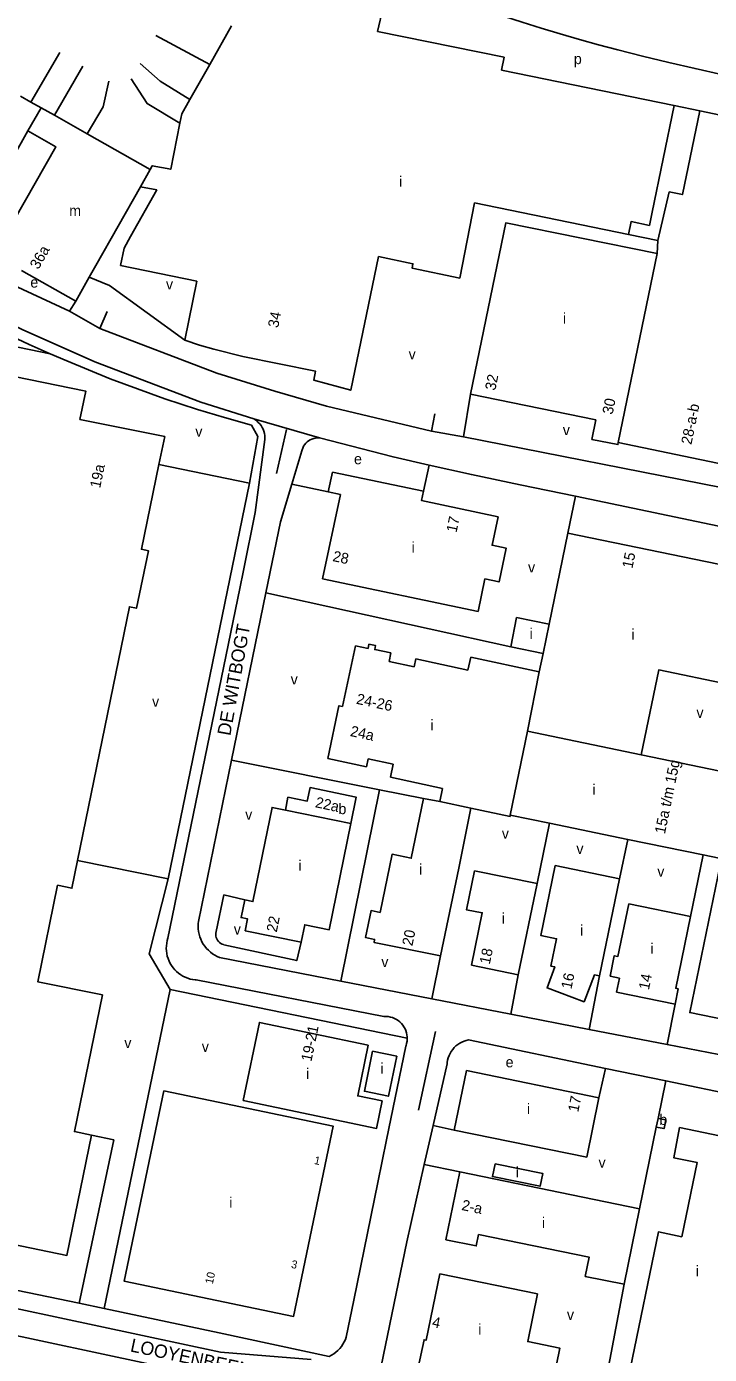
# Model space of a CAD drawing. Extents: x 157699 to 159683, y 381451 to 383293.
# Drawn here: x 158121.9 to 158378.5, y 382412.9 to 382912.1 of the extents above; entities that cross this region are included whole.
import ezdxf

# ---------------------------------------------------------------- set-up
doc = ezdxf.new("R2010")
doc.units = 0
for name, color, linetype in [('BLT_Basislijn', 7, 'Continuous'), ('BLT_Bebouwing', 7, 'Continuous'), ('BLT_Centroide', 7, 'Continuous'), ('BLT_Huisnummer', 7, 'Continuous'), ('BLT_Huisnummer_reeks', 7, 'Continuous'), ('BLT_Huisnummer_zonder_bebouwing', 7, 'Continuous'), ('BLT_Onderverdeling_panden', 7, 'Continuous'), ('BLT_Plantopo', 7, 'Continuous'), ('BLT_Straatnaam', 7, 'Continuous'), ('BLT_Vlakafsluiter', 7, 'Continuous')]:
    doc.layers.add(name, color=color, linetype=linetype)

msp = doc.modelspace()

# ---------------------------------------------------------------- linework, layer by layer
at = {"layer": 'BLT_Basislijn'}
for p, q in [((158170.52, 382908.69), (158190.73, 382897.79)), ((158134.47, 382902.3), (158123.51, 382883.71)), ((158143.12, 382897.15), (158132.36, 382878.72)), ((158365.26, 382882.45), (158374.91, 382880.36)), ((158374.91, 382880.36), (158410.62, 382872.97)), ((158348.09, 382833.93), (158359.11, 382831.68)), ((158359.11, 382831.68), (158358.91, 382826.72)), ((158153.11, 382814.79), (158145.48, 382817.84)), ((158181.37, 382794.18), (158153.11, 382814.79)), ((158066.51, 382802.08), (158130.82, 382789.08)), ((158288.77, 382773.83), (158286.11, 382757.88)), ((158219.56, 382760.56), (158215.88, 382744.12)), ((158286.11, 382757.88), (158382.94, 382738.83)), ((158211.43, 382756.88), (158207.86, 382729.4)), ((158225.36, 382752.63), (158221.58, 382740.04)), ((158271.09, 382737.39), (158273.16, 382747.23)), ((158175.13, 382591.65), (158205.69, 382740.41)), ((158221.58, 382740.04), (158217.35, 382725.93)), ((158235.29, 382737.16), (158221.58, 382740.04)), ((158328.18, 382735.5), (158307.46, 382739.82)), ((158325.37, 382721.64), (158328.18, 382735.5)), ((158410.45, 382718.37), (158328.18, 382735.5)), ((158203.38, 382707.6), (158207.86, 382729.4)), ((158217.35, 382725.93), (158211.88, 382699.26)), ((158203.38, 382707.6), (158202, 382700.87)), ((158202, 382700.87), (158175.02, 382569.41)), ((158211.88, 382699.26), (158198.96, 382636.32)), ((158303.85, 382678.9), (158211.88, 382699.26)), ((158198.96, 382636.32), (158186.5, 382575.59)), ((158198.96, 382636.32), (158254.52, 382625.1)), ((158271.1, 382621.91), (158254.52, 382625.1)), ((158313.75, 382589.93), (158318.49, 382612.56)), ((158249.98, 382602.82), (158239.99, 382553.27)), ((158344.72, 382591.73), (158347.83, 382606.52)), ((158376.2, 382600.68), (158371.43, 382577.47)), ((158168.01, 382563.5), (158175.13, 382591.65)), ((158175.92, 382550.09), (158168.01, 382563.5)), ((158194.44, 382562.13), (158239.99, 382553.27)), ((158277.52, 382562.68), (158274.2, 382546.62)), ((158185.61, 382553.66), (158256.21, 382539.93)), ((158239.99, 382553.27), (158274.2, 382546.62)), ((158306.71, 382555.65), (158303.91, 382540.84)), ((158337.21, 382555.17), (158333.36, 382535.11)), ((158174.41, 382542.8), (158175.92, 382550.09)), ((158264.97, 382531.75), (158175.92, 382550.09)), ((158151.05, 382430.2), (158174.41, 382542.8)), ((158274.2, 382546.62), (158303.91, 382540.84)), ((158365.62, 382544.54), (158362.62, 382529.42)), ((158303.91, 382540.84), (158333.36, 382535.11)), ((158275.65, 382534.29), (158269.2, 382504.67)), ((158333.36, 382535.11), (158362.62, 382529.42)), ((158264.4, 382528.72), (158257.23, 382493.62)), ((158288.04, 382531.15), (158339.51, 382520.44)), ((158362.62, 382529.42), (158419.43, 382518.37)), ((158336.93, 382509.32), (158339.51, 382520.44)), ((158339.51, 382520.44), (158362.15, 382515.73)), ((158359.22, 382501.62), (158362.15, 382515.73)), ((158362.15, 382515.73), (158440.61, 382499.4)), ((158282.61, 382497.22), (158274.7, 382499.01)), ((158352.25, 382467.67), (158358.54, 382498.35)), ((158257.23, 382493.62), (158253.94, 382477.52)), ((158284.75, 382481.5), (158271.37, 382484.25)), ((158079.72, 382444.87), (158141.73, 382432.11)), ((158337.32, 382391.27), (158346.43, 382439.27)), ((158167.06, 382409.46), (158078.71, 382428.33)), ((158141.73, 382432.11), (158151.05, 382430.2)), ((158151.05, 382430.2), (158194.34, 382420.96)), ((158194.34, 382420.96), (158235.68, 382412.15)), ((158228.89, 382411.03), (158194.81, 382413.76))]:
    msp.add_line(p, q, dxfattribs=at)
for points in [[(158344.05, 382903.29), (158336.84, 382905.22), (158329.65, 382907.23), (158322.49, 382909.31), (158315.35, 382911.47), (158308.22, 382913.7), (158301.13, 382916.01), (158294.06, 382918.4), (158287.01, 382920.87), (158279.99, 382923.4), (158273, 382926.02), (158266.04, 382928.71), (158259.11, 382931.47), (158252.21, 382934.31), (158245.33, 382937.22), (158238.49, 382940.2), (158231.68, 382943.26), (158224.91, 382946.39), (158219.94, 382948.75)], [(158432.83, 382884.22), (158422.84, 382886.04), (158412.88, 382887.94), (158402.92, 382889.92), (158392.99, 382891.97), (158383.07, 382894.1), (158373.17, 382896.31), (158363.28, 382898.6), (158353.41, 382900.97), (158344.05, 382903.29)], [(158164.55, 382898.18), (158172.17, 382891.59), (158183.28, 382884.62)], [(158161.25, 382892.41), (158167.23, 382883.14), (158179.55, 382875.74)], [(158152.81, 382891.59), (158150.75, 382881.9), (158144.73, 382871.74)], [(158130.82, 382789.08), (158122.95, 382792.52), (158103.06, 382801.86), (158093.21, 382806.75), (158070.33, 382818.61)], [(158207.29, 382764.61), (158187.44, 382770.88), (158147.52, 382786.08), (158120.25, 382798.17), (158071.88, 382821.87)], [(158138.07, 382805.1), (158117.02, 382814.81)], [(158140.4, 382808.83), (158138.07, 382805.1)], [(158152.23, 382804.94), (158149.43, 382798.58)], [(158149.43, 382798.58), (158193.46, 382781.8), (158215.23, 382775.05), (158234.68, 382769.4), (158274.12, 382759.98)], [(158205.69, 382740.41), (158208.77, 382757.97), (158206.39, 382762.19), (158196.25, 382765.08), (158186.13, 382768.18), (158173.93, 382772.19), (158153.39, 382779.68), (158137.04, 382786.36), (158130.82, 382789.08)], [(158207.29, 382764.61), (158208.4, 382763.81), (158209.01, 382763.29), (158209.56, 382762.71), (158210.04, 382762.07), (158210.46, 382761.39), (158210.81, 382760.67), (158211.09, 382759.92), (158211.29, 382759.15), (158211.42, 382758.36), (158211.46, 382757.56), (158211.43, 382756.88)], [(158274.12, 382759.98), (158275.37, 382766.54)], [(158231.99, 382757.52), (158230.51, 382757.38), (158229.82, 382757.24), (158229.15, 382757.01), (158228.51, 382756.72), (158227.9, 382756.35), (158227.35, 382755.92), (158226.84, 382755.43), (158226.39, 382754.88), (158226.01, 382754.29), (158225.7, 382753.65), (158225.45, 382752.99), (158225.36, 382752.63)], [(158273.16, 382747.23), (158259.62, 382750.28), (158231.99, 382757.52)], [(158171.64, 382747.4), (158205.69, 382740.41)], [(158307.46, 382739.82), (158289.11, 382743.64), (158273.16, 382747.23)], [(158254.52, 382625.1), (158249.98, 382602.82)], [(158141.08, 382598.6), (158175.13, 382591.65)], [(158203.89, 382583.79), (158196.07, 382585.67), (158193.19, 382571.86)], [(158194.44, 382562.13), (158193.52, 382562.54), (158192.63, 382563.01), (158191.79, 382563.55), (158190.99, 382564.16), (158190.24, 382564.83), (158189.54, 382565.56), (158188.91, 382566.34), (158188.34, 382567.17), (158187.84, 382568.04), (158187.41, 382568.95), (158187.05, 382569.89), (158186.77, 382570.86), (158186.56, 382571.84), (158186.43, 382572.84), (158186.39, 382573.85), (158186.42, 382574.85), (158186.5, 382575.59)], [(158175.02, 382569.41), (158174.76, 382568.47), (158174.57, 382567.51), (158174.46, 382566.53), (158174.42, 382565.55), (158174.47, 382564.57), (158174.6, 382563.6), (158174.81, 382562.64), (158175.09, 382561.7), (158175.45, 382560.79), (158175.89, 382559.91), (158176.39, 382559.07), (158176.96, 382558.27), (158177.6, 382557.52), (158178.29, 382556.83), (158179.03, 382556.19), (158179.83, 382555.62), (158180.67, 382555.11), (158181.55, 382554.68), (158182.46, 382554.31), (158183.4, 382554.03), (158184.36, 382553.82), (158185.33, 382553.68), (158185.61, 382553.66)], [(158193.19, 382571.86), (158193.08, 382571.31), (158193.05, 382570.74), (158193.09, 382570.18), (158193.22, 382569.63), (158193.43, 382569.1), (158193.7, 382568.61), (158194.05, 382568.15), (158194.45, 382567.76), (158194.9, 382567.42), (158195.4, 382567.15), (158195.93, 382566.95), (158196.07, 382566.92)], [(158196.07, 382566.92), (158223.47, 382560.94), (158225.12, 382567.88)], [(158256.21, 382539.93), (158257.02, 382539.95), (158257.83, 382539.88), (158258.62, 382539.74), (158259.4, 382539.52), (158260.15, 382539.22), (158260.88, 382538.85), (158261.56, 382538.42), (158262.19, 382537.91), (158262.77, 382537.35), (158263.29, 382536.73), (158263.75, 382536.06), (158264.15, 382535.35), (158264.46, 382534.61), (158264.71, 382533.84), (158264.88, 382533.05), (158264.96, 382532.24), (158264.97, 382531.75)], [(158264.97, 382531.75), (158264.97, 382531.43), (158264.9, 382530.62), (158264.75, 382529.83), (158264.52, 382529.05), (158264.4, 382528.72)], [(158288.04, 382531.15), (158287.17, 382530.95), (158286.33, 382530.67), (158285.51, 382530.32), (158284.72, 382529.9), (158283.98, 382529.4), (158283.28, 382528.85), (158282.64, 382528.23), (158282.05, 382527.55), (158281.53, 382526.83), (158281.07, 382526.06), (158280.68, 382525.26), (158280.37, 382524.42), (158280.13, 382523.56), (158279.97, 382522.68), (158279.92, 382522.19)], [(158279.92, 382522.19), (158274.7, 382499.01)], [(158274.7, 382499.01), (158271.37, 382484.25)], [(158141.73, 382432.11), (158154.7, 382493.56), (158146.31, 382495.33)], [(158271.37, 382484.25), (158264.83, 382455.22), (158255.23, 382408.53)], [(158253.94, 382477.52), (158244.92, 382433.33), (158242.07, 382419.4)], [(158194.81, 382413.76), (158103.17, 382433.33), (158050, 382444.69)], [(158242.07, 382419.4), (158241.72, 382418.47), (158241.3, 382417.57), (158240.8, 382416.71), (158240.24, 382415.89), (158239.61, 382415.12), (158238.93, 382414.4), (158238.18, 382413.74), (158237.39, 382413.14), (158236.55, 382412.61), (158235.68, 382412.15)]]:
    msp.add_lwpolyline(points, dxfattribs=at)
at = {"layer": 'BLT_Bebouwing'}
for p, q in [((158198.98, 382912.38), (158190.73, 382897.79)), ((158253.85, 382910.22), (158301.34, 382900.6)), ((158190.73, 382897.79), (158183.28, 382884.62)), ((158365.26, 382882.45), (158300.36, 382895.73)), ((158119.59, 382885.92), (158123.51, 382883.71)), ((158123.51, 382883.71), (158127.35, 382881.54)), ((158183.28, 382884.62), (158180.26, 382879.29)), ((158127.35, 382881.54), (158132.36, 382878.72)), ((158132.36, 382878.72), (158144.73, 382871.74)), ((158180.26, 382879.29), (158179.55, 382875.74)), ((158122.44, 382872.85), (158102.78, 382838.01)), ((158164.68, 382851.86), (158148, 382822.3)), ((158284.68, 382817.44), (158290.23, 382845.77)), ((158290.23, 382845.77), (158348.09, 382833.93)), ((158148, 382822.3), (158145.48, 382817.84)), ((158358.91, 382826.72), (158344.3, 382755.69)), ((158140.4, 382808.83), (158120.03, 382820.33)), ((158145.48, 382817.84), (158140.4, 382808.83)), ((158335.86, 382764.23), (158288.77, 382773.83)), ((158236.84, 382744.62), (158235.29, 382737.16)), ((158271.09, 382737.39), (158236.84, 382744.62)), ((158239.85, 382736.2), (158233.14, 382704.51)), ((158235.29, 382737.16), (158239.85, 382736.2)), ((158318.27, 382687.39), (158325.37, 382721.64)), ((158233.14, 382704.51), (158291.57, 382692.24)), ((158315.99, 382676.39), (158318.27, 382687.39)), ((158245.49, 382679.23), (158240.59, 382656.49)), ((158250.23, 382678.24), (158245.49, 382679.23)), ((158250.59, 382679.9), (158250.23, 382678.24)), ((158303.85, 382678.9), (158315.99, 382676.39)), ((158258.12, 382673.44), (158258.8, 382676.59)), ((158267.56, 382671.42), (158258.12, 382673.44)), ((158268.19, 382674.38), (158267.56, 382671.42)), ((158287.78, 382670.18), (158268.19, 382674.38)), ((158288.83, 382675.05), (158287.78, 382670.18)), ((158314.56, 382669.46), (158288.83, 382675.05)), ((158314.56, 382669.46), (158315.99, 382676.39)), ((158352.94, 382638.28), (158391.62, 382630.22)), ((158235.07, 382636.97), (158249.62, 382633.84)), ((158249.62, 382633.84), (158250.27, 382636.79)), ((158250.27, 382636.79), (158259.7, 382634.76)), ((158259.7, 382634.76), (158258.64, 382629.89)), ((158258.64, 382629.89), (158278.25, 382625.65)), ((158278.25, 382625.65), (158277.18, 382620.79)), ((158277.18, 382620.79), (158271.1, 382621.91)), ((158284.32, 382595.75), (158288.86, 382618.28)), ((158288.86, 382618.28), (158303.59, 382615.12)), ((158303.59, 382615.12), (158303.69, 382615.6)), ((158277.52, 382562.68), (158284.32, 382595.75)), ((158290.24, 382594.75), (158313.75, 382589.93)), ((158320.62, 382596.68), (158344.72, 382591.73)), ((158313.75, 382589.93), (158306.71, 382555.65)), ((158344.72, 382591.73), (158337.21, 382555.17)), ((158371.43, 382577.47), (158348.21, 382582.26)), ((158344.79, 382554.38), (158341.23, 382555.1)), ((158344.79, 382554.38), (158343.65, 382549.05)), ((158365.62, 382544.54), (158343.65, 382549.05)), ((158365.62, 382544.54), (158366.84, 382550.37)), ((158287.2, 382519.58), (158282.61, 382497.22)), ((158287.2, 382519.58), (158336.93, 382509.32)), ((158358.54, 382498.35), (158359.22, 382501.62)), ((158332.4, 382487), (158282.61, 382497.22)), ((158284.75, 382481.5), (158352.25, 382467.67)), ((158352.25, 382467.67), (158346.45, 382439.33)), ((158346.45, 382439.33), (158346.43, 382439.27))]:
    msp.add_line(p, q, dxfattribs=at)
for points in [[(158253.85, 382910.22), (158255.87, 382919.19), (158208.12, 382928.54)], [(158300.36, 382895.73), (158301.34, 382900.6)], [(158356.04, 382837.35), (158357.04, 382842.25), (158365.26, 382882.45)], [(158117.43, 382839.55), (158132.86, 382866.89), (158122.44, 382872.85)], [(158179.55, 382875.74), (158176.07, 382858.46), (158169.12, 382859.73), (158168.37, 382858.4)], [(158144.73, 382871.74), (158168.37, 382858.4)], [(158164.68, 382851.86), (158170.86, 382850.67), (158161.03, 382833.18), (158158.58, 382828.82), (158157.27, 382822.3)], [(158288.77, 382773.83), (158301.98, 382838.26), (158358.91, 382826.72)], [(158348.09, 382833.93), (158349.08, 382838.78), (158356.04, 382837.35)], [(158157.27, 382822.3), (158185.9, 382816.36), (158181.37, 382794.18)], [(158181.37, 382794.18), (158186.85, 382792.35), (158192.23, 382790.76), (158203.14, 382788.1), (158230.53, 382782.48), (158229.87, 382779.1), (158243.75, 382775.34), (158254.12, 382825.6)], [(158254.12, 382825.6), (158267.12, 382822.94), (158266.78, 382821.3), (158284.68, 382817.44)], [(158171.64, 382747.4), (158173.82, 382757.93), (158141.98, 382764.41), (158144.22, 382774.98), (158074.33, 382789.35), (158073.25, 382784), (158068, 382785.1), (158065.73, 382774.05), (158070.97, 382772.97), (158065.05, 382744.09)], [(158344.3, 382755.69), (158344.13, 382754.91), (158334.35, 382756.91), (158335.86, 382764.23)], [(158141.08, 382598.6), (158160.57, 382693.95), (158163.22, 382693.4), (158167.71, 382715.01), (158165.05, 382715.56), (158171.64, 382747.4)], [(158299.12, 382727.79), (158270.37, 382733.89), (158271.09, 382737.39)], [(158291.57, 382692.24), (158294.17, 382704.46), (158299.49, 382703.32), (158302.18, 382715.96), (158296.85, 382717.09), (158299.12, 382727.79)], [(158325.37, 382721.64), (158394.7, 382707.39), (158385.9, 382664.78), (158359.46, 382670.22), (158352.94, 382638.28)], [(158318.27, 382687.39), (158306.06, 382689.92), (158303.85, 382678.9)], [(158258.8, 382676.59), (158252.77, 382677.89), (158253.1, 382679.35), (158250.59, 382679.9)], [(158240.59, 382656.49), (158239.32, 382656.76), (158235.07, 382636.97)], [(158219.17, 382617.54), (158220.15, 382622.37), (158227.41, 382620.89), (158228.44, 382625.97), (158245.77, 382622.45), (158243.76, 382612.55)], [(158203.89, 382583.79), (158206.99, 382583.15), (158214.19, 382618.55), (158219.17, 382617.54)], [(158271.1, 382621.91), (158266.46, 382599.44), (158259.25, 382600.93), (158254.78, 382579.05), (158251.4, 382579.74), (158249.33, 382569.61), (158252.71, 382568.92), (158252.48, 382567.79), (158277.52, 382562.68)], [(158318.49, 382612.56), (158303.69, 382615.6)], [(158243.76, 382612.55), (158235.64, 382572.55), (158226.44, 382574.42), (158225.12, 382567.88)], [(158347.83, 382606.52), (158318.49, 382612.56)], [(158376.2, 382600.68), (158347.83, 382606.52)], [(158133.59, 382589.26), (158138.95, 382588.16), (158141.08, 382598.6)], [(158385.16, 382598.84), (158376.2, 382600.68)], [(158306.71, 382555.65), (158289.13, 382559.27), (158293.14, 382578.91), (158287.24, 382580.09), (158290.24, 382594.75)], [(158337.21, 382555.17), (158335.3, 382555.59), (158331.44, 382545.45), (158317.51, 382550.68), (158320.39, 382558.62), (158318.99, 382558.9), (158321.09, 382569.15), (158315.21, 382570.33), (158320.62, 382596.68)], [(158382.54, 382596.85), (158371.13, 382541.39), (158393.66, 382536.76), (158405.05, 382592.21)], [(158146.31, 382495.33), (158139.87, 382496.65), (158150.39, 382548.03), (158126.13, 382552.99), (158133.59, 382589.26)], [(158225.12, 382567.88), (158204.08, 382572.15), (158204.99, 382576.62), (158202.53, 382577.12), (158203.89, 382583.79)], [(158348.21, 382582.26), (158344.15, 382562.5), (158342.74, 382562.79), (158341.23, 382555.1)], [(158371.43, 382577.47), (158365.9, 382550.57), (158366.84, 382550.37)], [(158250.34, 382529.21), (158209.43, 382537.71), (158203.37, 382508.38)], [(158255.51, 382508.26), (158246.36, 382510.1), (158250.34, 382529.21)], [(158251.95, 382526.88), (158261.01, 382525.01), (158257.91, 382509.98), (158248.85, 382511.85), (158251.95, 382526.88)], [(158203.37, 382508.38), (158253.42, 382497.84), (158255.51, 382508.26)], [(158336.93, 382509.32), (158332.4, 382487)], [(158359.22, 382501.62), (158362.17, 382501.04), (158361.52, 382497.8), (158358.54, 382498.35)], [(158398.01, 382491.76), (158367.33, 382498.18), (158365.12, 382486.84), (158373.94, 382485.02), (158368.21, 382457.15)], [(158092.15, 382459.38), (158137.1, 382450.14), (158146.31, 382495.33)], [(158346.43, 382439.27), (158331.87, 382442.25), (158333.35, 382449.44), (158291.81, 382457.96), (158290.93, 382453.68), (158279.52, 382456.02), (158284.75, 382481.5)], [(158368.21, 382457.15), (158359.39, 382458.96), (158348.75, 382407.31), (158379.37, 382401)], [(158277.24, 382443.21), (158272.08, 382418.25), (158271.28, 382418.42), (158269.12, 382407.98)], [(158313.96, 382435.7), (158277.24, 382443.21)], [(158306.63, 382399.96), (158318.68, 382397.49), (158322.32, 382415.25), (158310.27, 382417.72), (158313.96, 382435.7)]]:
    msp.add_lwpolyline(points, dxfattribs=at)
for points in [[(158173.51, 382511.96), (158237.17, 382498.66), (158222.24, 382427.21), (158158.59, 382440.49)], [(158297.98, 382484.59), (158296.99, 382479.77), (158314.9, 382476.1), (158315.89, 382480.92)]]:
    msp.add_lwpolyline(points, close=True, dxfattribs=at)
at = {"layer": 'BLT_Onderverdeling_panden'}
for p, q in [((158122.44, 382872.85), (158127.35, 382881.54)), ((158164.68, 382851.86), (158168.37, 382858.4)), ((158310.13, 382647.23), (158314.56, 382669.46)), ((158303.69, 382615.6), (158310.13, 382647.23)), ((158352.94, 382638.28), (158310.13, 382647.23)), ((158277.18, 382620.79), (158288.86, 382618.28)), ((158219.17, 382617.54), (158243.76, 382612.55))]:
    msp.add_line(p, q, dxfattribs=at)
at = {"layer": 'BLT_Plantopo'}
msp.add_line((158344.3, 382755.69), (158384.61, 382747.34), dxfattribs=at)
msp.add_lwpolyline([(158374.91, 382880.36), (158368.39, 382848.9), (158363.46, 382849.92), (158359.11, 382831.68)], dxfattribs=at)
at = {"layer": 'BLT_Vlakafsluiter'}
for p, q in [((158138.07, 382805.1), (158149.43, 382798.58)), ((158207.29, 382764.61), (158231.99, 382757.52)), ((158274.12, 382759.98), (158286.11, 382757.88))]:
    msp.add_line(p, q, dxfattribs=at)

# ---------------------------------------------------------------- texts
at = {"layer": 'BLT_Centroide'}
for s, p in [('p', (158327.59, 382897.96)), ('i', (158261.88, 382851.84)), ('m', (158137.94, 382840.9)), ('e', (158123.32, 382813.96)), ('v', (158174.3, 382813.25)), ('i', (158323.47, 382800.41)), ('v', (158265.49, 382786.94)), ('v', (158185.34, 382757.88)), ('v', (158323.43, 382758.48)), ('e', (158244.97, 382747.54)), ('i', (158266.62, 382714.31)), ('v', (158310.37, 382706.85)), ('i', (158310.94, 382681.91)), ('i', (158349.2, 382681.59)), ('v', (158221.17, 382664.75)), ('v', (158169.07, 382656.37)), ('v', (158373.65, 382652.17)), ('i', (158273.73, 382647.5)), ('i', (158334.53, 382623.27)), ('b', (158239.12, 382616.01)), ('v', (158204.07, 382613.89)), ('v', (158300.51, 382606.76)), ('v', (158328.54, 382601.06)), ('i', (158224.11, 382594.72)), ('i', (158269.42, 382593.31)), ('v', (158358.95, 382592.5)), ('i', (158300.5, 382574.86)), ('v', (158199.79, 382570.76)), ('i', (158329.97, 382570.38)), ('i', (158356.33, 382563.52)), ('v', (158255.23, 382558.51)), ('v', (158158.65, 382528.04)), ('v', (158187.76, 382526.61)), ('e', (158301.94, 382520.82)), ('i', (158226.99, 382516.44)), ('i', (158254.92, 382518.44)), ('i', (158309.95, 382503.25)), ('b', (158359.7, 382499.15)), ('i', (158305.71, 382479.42)), ('v', (158336.85, 382483.05)), ('i', (158198.07, 382468.01)), ('i', (158315.59, 382460.41)), ('i', (158373.39, 382442.28)), ('v', (158324.98, 382425.87)), ('i', (158291.66, 382420.34))]:
    msp.add_text(s, height=4, dxfattribs=at).set_placement(p)
at = {"layer": 'BLT_Huisnummer'}
for s, rotation, p in [('36a', 60.565, (158126.37, 382820.54)), ('34', 78.5456, (158216.46, 382798.62)), ('32', 78.456, (158298.05, 382775.07)), ('30', 78.456, (158342.13, 382766.06)), ('15', 78.2948, (158349.57, 382708.14)), ('20', 78.4525, (158266.9, 382566.26)), ('18', 77.9597, (158295.96, 382559.32)), ('16', 78.1755, (158326.65, 382550.02)), ('14', 78.4525, (158355.78, 382549.72)), ('17', 78.3507, (158329.22, 382503.78)), ('4', 348.2631, (158274.09, 382423.28))]:
    msp.add_text(s, height=4, rotation=rotation, dxfattribs=at).set_placement(p)
at = {"layer": 'BLT_Huisnummer_reeks'}
for s, height, rotation, p in [('19a', 4, 78.2853, (158149.56, 382738.34)), ('17', 4, 78.0035, (158283.48, 382721.66)), ('28', 4, 348.1463, (158236.71, 382711.18)), ('24-26', 4, 347.8679, (158245.59, 382657.54)), ('24a', 4, 347.8423, (158243.3, 382645.42)), ('15a t/m 15g', 4, 78.3715, (158361.81, 382608.36)), ('22a', 4, 347.8423, (158230.17, 382618.65)), ('22', 4, 78.7494, (158215.93, 382571.42)), ('19-21', 4, 78.2853, (158228.94, 382522.77)), ('1', 3, 348.2184, (158229.79, 382484.54)), ('2-a', 4, 348.2631, (158285.18, 382467.23)), ('3', 3, 348.2184, (158221.15, 382445.48)), ('10', 3, 78.2184, (158191.9, 382439.16))]:
    msp.add_text(s, height=height, rotation=rotation, dxfattribs=at).set_placement(p)
at = {"layer": 'BLT_Huisnummer_zonder_bebouwing'}
msp.add_text('28-a-b', height=4, rotation=78.5113, dxfattribs=at).set_placement((158371.76, 382754.71))
at = {"layer": 'BLT_Straatnaam'}
for s, height, rotation, p in [('DE WITBOGT', 5, 79.7595, (158198.47, 382645.25)), ('LOOYENBEEMD', 4.9999, 347.9979, (158160.62, 382414.06))]:
    msp.add_text(s, height=height, rotation=rotation, dxfattribs=at).set_placement(p)

doc.saveas('drawing.dxf')
